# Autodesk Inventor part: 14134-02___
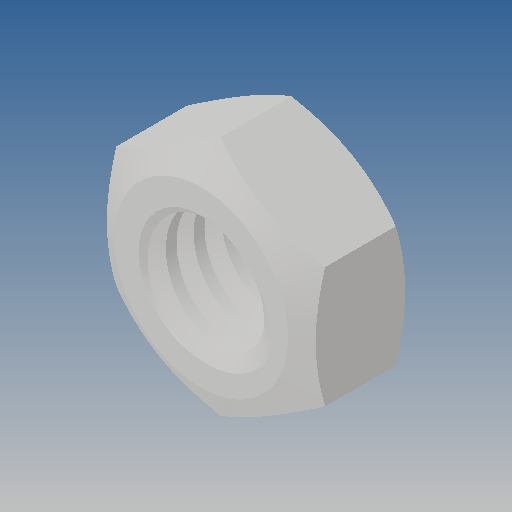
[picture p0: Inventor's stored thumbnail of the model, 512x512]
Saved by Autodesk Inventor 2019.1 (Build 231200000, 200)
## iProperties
Created: 2010-06
Part Number: 14134-02___
Material: Ogólny
Document SubType Name: Modeling
Designer: CADENGINEERING4
Density: 1 g/cm^3
Appearance: Domyślna
Author: CADENGINEERING4
Revision Number: ANY
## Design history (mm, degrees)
feature "NONE"
node "Bryła1"
